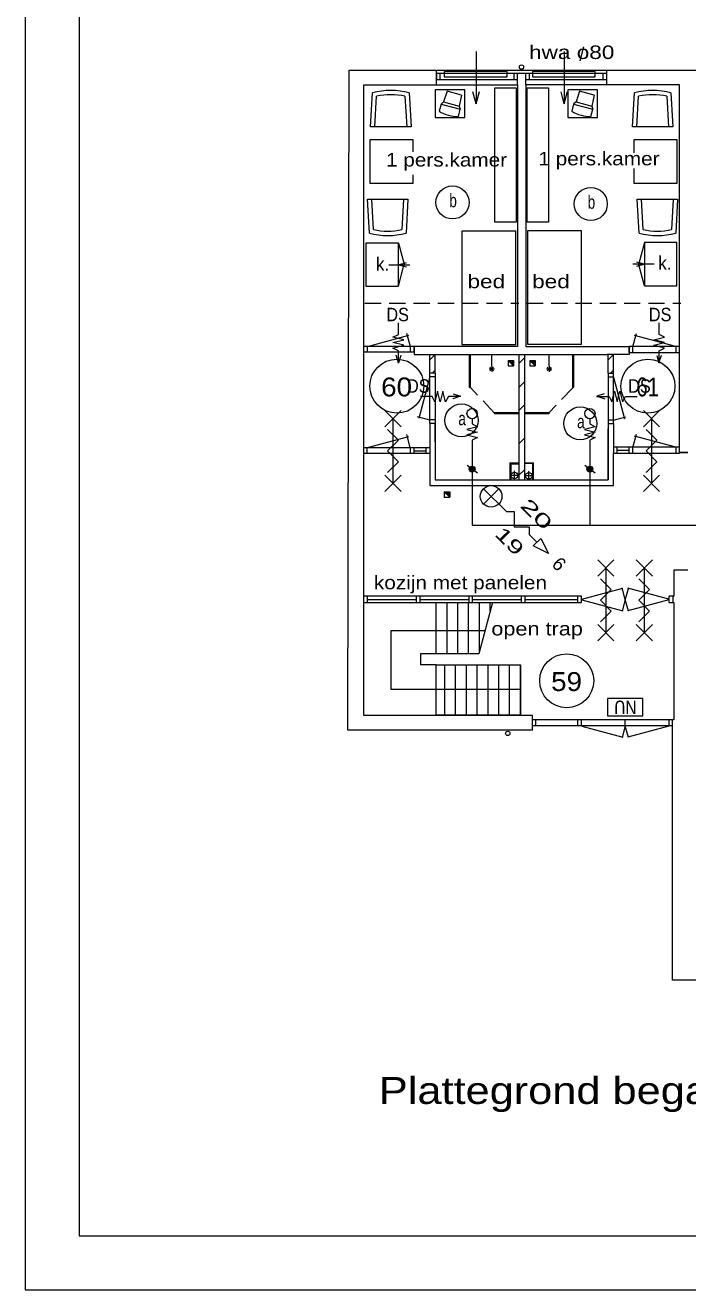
# Model space of a CAD drawing. Extents: x 295824 to 414724, y 24924 to 109024.
# Drawn here: x 295824 to 308090, y 24924 to 48360 of the extents above; entities that cross this region are included whole.
import ezdxf
from ezdxf.enums import TextEntityAlignment as Align

# ---------------------------------------------------------------- set-up
doc = ezdxf.new("R2010")
doc.units = 0
doc.header["$LTSCALE"] = 100
doc.linetypes.add('DOT_DASHED', pattern=[7.7, 5, -1.2, 0.3, -1.2])
doc.linetypes.add('MEDIUM_DASHED', pattern=[4.5, 3, -1.5])
for name, color, linetype, lineweight in [('1', 7, 'Continuous', 13), ('16', 7, 'Continuous', 13), ('24', 7, 'Continuous', 13), ('61', 7, 'Continuous', 13)]:
    doc.layers.add(name, color=color, linetype=linetype, lineweight=lineweight)

msp = doc.modelspace()

# ---------------------------------------------------------------- hatches: boundary and pattern name
at = {"layer": '24'}
for points in [[(304151.5, 40135, 1), (304042.9, 40135, 1)], [(306333.5, 40135, 1), (306224.9, 40135, 1)]]:
    msp.add_hatch(color=256, dxfattribs=at).paths.add_polyline_path(points)
at = {"layer": '61'}
for points in [[(304864.2, 42048.6), (304764.2, 42148.6), (304864.2, 42148.6)], [(305267.2, 42048.6), (305167.2, 42148.6), (305267.2, 42148.6)], [(303682.7, 39611.2), (303582.7, 39711.2), (303682.7, 39711.2)]]:
    msp.add_hatch(color=256, dxfattribs=at).paths.add_polyline_path(points)

# ---------------------------------------------------------------- linework, layer by layer
at = {"layer": '1'}
for p, q in [((295823.6, 109023.8), (295823.6, 24923.8)), ((304097.2, 40103.6), (304097.2, 39093.2)), ((306279.2, 40097), (306279.2, 39093.2)), ((295823.6, 24923.8), (304995.6, 24923.8)), ((304995.6, 24923.8), (414723.6, 24923.8))]:
    msp.add_line(p, q, dxfattribs=at)
for points in [[(304995.6, 108023.8), (296823.6, 108023.8), (296823.6, 25923.8), (304995.6, 25923.8)], [(304995.6, 25923.8), (413723.6, 25923.8), (413723.6, 108023.8), (304995.6, 108023.8)]]:
    msp.add_lwpolyline(points, dxfattribs=at)
at = {"layer": '16'}
for p, q in [((302631.4, 42478.5), (302831.4, 42528.5)), ((307661.7, 42478.5), (307461.7, 42528.5)), ((303507.8, 41380.3), (303457.8, 41580.3)), ((306785.3, 41380.3), (306835.3, 41580.3))]:
    msp.add_line(p, q, dxfattribs=at)
at = {"layer": '24'}
for p, q in [((304172.2, 46901.4), (304112.5, 47123.8)), ((305804.5, 46901.4), (305744.9, 47123.8)), ((302734.8, 42103.1), (302689.8, 42247.3)), ((302777.2, 42238.9), (302734.8, 42103.1)), ((307515.9, 42238.9), (307558.3, 42103.1)), ((307558.3, 42103.1), (307603.3, 42247.3)), ((303883.2, 41483.7), (303739, 41438.7)), ((303747.4, 41526.2), (303883.2, 41483.7)), ((306545.7, 41526.2), (306409.9, 41483.7)), ((306409.9, 41483.7), (306554, 41438.7)), ((304097.2, 40620.3), (304097.2, 40080.9)), ((306279.2, 40620.3), (306279.2, 40112)), ((304005.6, 40205.8), (304197.1, 40064.1)), ((306187.6, 40205.8), (306379.1, 40064.1)), ((304097.2, 39093.2), (328693.9, 39093.2))]:
    msp.add_line(p, q, dxfattribs=at)
for points in [[(304172.2, 47876.3), (304172.2, 46901.4), (304233.8, 47131.6)], [(305804.5, 47876.3), (305804.5, 46901.4), (305866.2, 47131.6)], [(302831.4, 42528.5), (302631.4, 42578.5), (302731.4, 42628.5), (302731.4, 42847.3)], [(307461.7, 42528.5), (307661.7, 42578.5), (307561.7, 42628.5), (307561.7, 42847.3)], [(302731.4, 42097.3), (302731.4, 42328.5), (302631.4, 42378.5), (302831.4, 42428.5), (302631.4, 42478.5)], [(307561.7, 42097.3), (307561.7, 42328.5), (307661.7, 42378.5), (307461.7, 42428.5), (307661.7, 42478.5)], [(303457.8, 41580.3), (303407.8, 41380.3), (303357.8, 41480.3), (303139.1, 41480.3)], [(303889.1, 41480.3), (303657.8, 41480.3), (303607.8, 41380.3), (303557.8, 41580.3), (303507.8, 41380.3)], [(306404, 41480.3), (306635.3, 41480.3), (306685.3, 41380.3), (306735.3, 41580.3), (306785.3, 41380.3)], [(306835.3, 41580.3), (306885.3, 41380.3), (306935.3, 41480.3), (307154, 41480.3)], [(304097.2, 41070.3), (304097.2, 40970.3), (304197.2, 40920.3), (303997.2, 40870.3), (304197.2, 40820.3), (303997.2, 40770.3), (304197.2, 40720.3), (304097.2, 40670.3), (304097.2, 40620.3)], [(306279.2, 41070.3), (306279.2, 40970.3), (306379.2, 40920.3), (306179.2, 40870.3), (306379.2, 40820.3), (306179.2, 40770.3), (306379.2, 40720.3), (306279.2, 40670.3), (306279.2, 40620.3)]]:
    msp.add_lwpolyline(points, dxfattribs=at)
for points in [[(303580.8, 47405.5), (304746.8, 47405.5), (304746.8, 47505.5), (303580.8, 47505.5)], [(305213.2, 47405.5), (306379.1, 47405.5), (306379.1, 47505.5), (305213.2, 47505.5)]]:
    msp.add_lwpolyline(points, close=True, dxfattribs=at)
for centre, radius in [((304097.2, 41162), 95), ((306279.2, 41162), 95), ((304097.2, 40135), 54.3), ((306279.2, 40135), 54.3)]:
    msp.add_circle(centre, radius, dxfattribs=at)
at = {"layer": '61'}
for p, q in [((301796.6, 35294.8), (301820.1, 47527.9)), ((301828.9, 47527.9), (333452, 47527.9)), ((303440.8, 47257.3), (303440.8, 47527.3)), ((303441.6, 47472.1), (304940.6, 47472.1)), ((303441.6, 47358.1), (303441.6, 47472.1)), ((303441.6, 47358.1), (304939.7, 47358.1)), ((303508.6, 47358.1), (303508.6, 47471.5)), ((304873.6, 47472.1), (306589.6, 47472.1)), ((304873.6, 47358.5), (304873.6, 47472.1)), ((304940.6, 47359.1), (304940.6, 47472.1)), ((304940.8, 47257.3), (304940.8, 47472.1)), ((305089.8, 47257.3), (305089.8, 47472.1)), ((305090.6, 47358.1), (305090.6, 47472.1)), ((305090.6, 47358.1), (306588.7, 47358.1)), ((305157.6, 47358.1), (305157.6, 47471.5)), ((306522.6, 47358.5), (306522.6, 47471.5)), ((306589.6, 47359.1), (306589.6, 47472.1)), ((306589.8, 47257.3), (306589.8, 47527.3)), ((302090.1, 40535.6), (302090.1, 47257.9)), ((302218.1, 46478.4), (302253, 47107.7)), ((303632.8, 47140.4), (303568.8, 46940.1)), ((303903.3, 47067.9), (303632.8, 47140.4)), ((306088.6, 47140.4), (306024.6, 46940.1)), ((306359, 47067.9), (306088.6, 47140.4)), ((307067.6, 46478.4), (307102.6, 47107.7)), ((307940.1, 40540.2), (307940.1, 47257.9)), ((302298.2, 46478.4), (302329.6, 47044.3)), ((302854.4, 47044.2), (302887.9, 46478.4)), ((303522.1, 46900.8), (303485.9, 46765.9)), ((303568.8, 46940.1), (303522.1, 46900.8)), ((303522.1, 46900.8), (303879.5, 46805.1)), ((303903.3, 47067.9), (303858.6, 46862.5)), ((305977.8, 46900.8), (305941.7, 46765.9)), ((306024.6, 46940.1), (305977.8, 46900.8)), ((305977.8, 46900.8), (306335.2, 46805.1)), ((306359, 47067.9), (306314.4, 46862.5)), ((307147.8, 46478.4), (307179.2, 47044.3)), ((307704, 47044.2), (307737.5, 46478.4)), ((303843.2, 46669.8), (303879.5, 46805.1)), ((306299, 46669.8), (306335.2, 46805.1)), ((303004.6, 46013), (303004.6, 46235.3)), ((307095.4, 45707.2), (307095.4, 45435.3)), ((303004.6, 45435.3), (303004.6, 45590.5)), ((302204.6, 45435.3), (303004.6, 45435.3)), ((302273, 44572.7), (302239.6, 45138.5)), ((302829.2, 45138.5), (302797.8, 44572.6)), ((302909.4, 45138.5), (302874.4, 44509.2)), ((307267.1, 44572.7), (307233.6, 45138.5)), ((307823.3, 45138.5), (307791.9, 44572.6)), ((307903.4, 45138.5), (307868.5, 44509.2)), ((302732.3, 44322.5), (302836.7, 43932.9)), ((307287.9, 44331.3), (307184.6, 43945.7)), ((302552.5, 43922.5), (302946.8, 43922.5)), ((302732.3, 43922.5), (302880.1, 43962)), ((302732.3, 43922.5), (302880.6, 43882.7)), ((302732.3, 43522.5), (302835.7, 43908.1)), ((307467.7, 43931.3), (307073.4, 43931.3)), ((307287.9, 43931.3), (307139.6, 43971)), ((307287.9, 43931.3), (307140.2, 43891.7)), ((307287.9, 43531.3), (307183.5, 43920.9)), ((302160.1, 42409.2), (302927.4, 42614.8)), ((302954.7, 42407.1), (302889.7, 42649.8)), ((307076.5, 42405.1), (307141.5, 42647.8)), ((307871.1, 42407.2), (307103.8, 42612.8)), ((303022.4, 42299.4), (302091.6, 42299.4)), ((302157.5, 42299.1), (302157.5, 42409.1)), ((302957.5, 42299.1), (302957.5, 42409.1)), ((303024.5, 42299.1), (303024.5, 42409.1)), ((303025.4, 42257.9), (306615.6, 42257.9)), ((303315.2, 41911.5), (303315.2, 42257.9)), ((303315.2, 42157.2), (303415.7, 42257.6)), ((303414, 41911.5), (303414, 42257.9)), ((304047.9, 41644.6), (304047.9, 42253)), ((304065.9, 41644.6), (304065.9, 42253)), ((304460.8, 42039.2), (304460.8, 42239.2)), ((304965.1, 42257.9), (304965.1, 39932.9)), ((304965.6, 42093), (305064.1, 42191.5)), ((305065.1, 42257.9), (305065.1, 39932.9)), ((305525.3, 42039.2), (305525.3, 42239.2)), ((305965.7, 41650.7), (305965.7, 42255.5)), ((305983.7, 41650.7), (305983.7, 42255.5)), ((306615.6, 41911.9), (306615.6, 42258.3)), ((306615.7, 42157.2), (306716.2, 42257.6)), ((306715.4, 41911.5), (306715.4, 42257.9)), ((307006.7, 42297.1), (307006.7, 42407.1)), ((307008.8, 42297.4), (307939.6, 42297.4)), ((307073.7, 42297.1), (307073.7, 42407.1)), ((307873.7, 42297.1), (307873.7, 42407.1)), ((303357.6, 41913.2), (303414.3, 41969.9)), ((304510.8, 41989.2), (304410.8, 41989.2)), ((304496.2, 42024.5), (304425.4, 41953.8)), ((304496.2, 41953.8), (304425.4, 42024.5)), ((304460.8, 42039.2), (304460.8, 41939.2)), ((305575.3, 41989.2), (305475.3, 41989.2)), ((305560.6, 42024.5), (305489.9, 41953.8)), ((305560.6, 41953.8), (305489.9, 42024.5)), ((305525.3, 42039.2), (305525.3, 41939.2)), ((306659.5, 41913.2), (306716.2, 41969.9)), ((303315.3, 41841.3), (303108.4, 41069.1)), ((303315, 40977.9), (303315, 41911.9)), ((303415, 41911.9), (303315, 41911.9)), ((303415.2, 41844.9), (303315, 41844.9)), ((303415, 41911.9), (303415, 40977.9)), ((304965.6, 41645.4), (305064.1, 41743.9)), ((306615, 41844.5), (306715.1, 41844.5)), ((306615.1, 41911.5), (306615.1, 40977.5)), ((306615.6, 41911.5), (306715.7, 41911.5)), ((306714.9, 41841), (306921.8, 41068.7)), ((306715.1, 40976.7), (306715.1, 41911.5)), ((304047.9, 41644.6), (304065.9, 41644.6)), ((305965.7, 41650.7), (305983.7, 41650.7)), ((306715.2, 41578.4), (306715.2, 41468)), ((304965.6, 41222.9), (305064.1, 41321.4)), ((302482.1, 40919.8), (302782.1, 41219.8)), ((302782.1, 40919.8), (302482.1, 41219.8)), ((302632.1, 41069.8), (302632.1, 39869.8)), ((303315.3, 41043.9), (303088, 41104.8)), ((303414.9, 41044.9), (303315.5, 41044.9)), ((304964.8, 41158.7), (304514.4, 41158.7)), ((305516.2, 41176.7), (305066.1, 41176.7)), ((305516.2, 41158.7), (305066.1, 41158.7)), ((305516.2, 41176.7), (305516.2, 41158.7)), ((306615.3, 41044.5), (306714.6, 41044.5)), ((306714.9, 41043.5), (306942.2, 41104.4)), ((307269.7, 40919.8), (307569.7, 41219.8)), ((307569.7, 40919.8), (307269.7, 41219.8)), ((307419.7, 41069.8), (307419.7, 39869.8)), ((303415, 40977.9), (303315, 40977.9)), ((303315.1, 40975.3), (303315.1, 40188.2)), ((303415.1, 40638.2), (303415.1, 40975.3)), ((306615.1, 40977.5), (306615.1, 39932.9)), ((306615.1, 40977.5), (306715.1, 40977.5)), ((306715.1, 40977.5), (306715.1, 40532.9)), ((307076.5, 40536.8), (307141.5, 40779.5)), ((302158.9, 40535.1), (302926.2, 40740.7)), ((302953.5, 40532.9), (302888.4, 40775.7)), ((304965.6, 40603), (305064.1, 40701.4)), ((307871.1, 40539), (307103.8, 40744.6)), ((302090.1, 37776.3), (302090.1, 40424.1)), ((302156.3, 40424.9), (302156.3, 40534.9)), ((302956.3, 40424.9), (302956.3, 40534.9)), ((303023.3, 40424.9), (303023.3, 40534.9)), ((303024.1, 40475.7), (303248.8, 40475.7)), ((303248.8, 40424.9), (303248.8, 40534.9)), ((306781.2, 40428.8), (306781.2, 40538.8)), ((307005.8, 40479.6), (306781.2, 40479.6)), ((307006.7, 40428.8), (307006.7, 40538.8)), ((307073.7, 40428.8), (307073.7, 40538.8)), ((307873.7, 40428.8), (307873.7, 40538.8)), ((307939.5, 40447.3), (308089.5, 40447.3)), ((307939.5, 40443.5), (308089.5, 40443.5)), ((304797.5, 40248.9), (304965.3, 40248.9)), ((304797.5, 40248.9), (304797.5, 39935.2)), ((304812.5, 40233.9), (304964.4, 40233.9)), ((304812.5, 40233.9), (304812.5, 39934.9)), ((304967.7, 40024.9), (305065, 40122.2)), ((305065.1, 40250.3), (305235.7, 40250.3)), ((305220.8, 40235.1), (305065.1, 40235.1)), ((305220.8, 39933.5), (305220.8, 40235.1)), ((305235.7, 39932.9), (305235.7, 40250.3)), ((302482.1, 39719.8), (302782.1, 40019.8)), ((302782.1, 39719.8), (302482.1, 40019.8)), ((307269.7, 39719.8), (307569.7, 40019.8)), ((307569.7, 39719.8), (307269.7, 40019.8)), ((304591, 39769.8), (304308.1, 39487)), ((306423.7, 38152.6), (306723.7, 38452.6)), ((306723.7, 38152.6), (306423.7, 38452.6)), ((307135.6, 38152.6), (307435.6, 38452.6)), ((307435.6, 38152.6), (307135.6, 38452.6)), ((306573.7, 38302.6), (306573.7, 37102.6)), ((307285.6, 38302.6), (307285.6, 37102.6)), ((306122.8, 37776.3), (302090.1, 37776.3)), ((302092, 37664.3), (302092, 37776.3)), ((302159, 37663.7), (302159, 37775.7)), ((303067.5, 37663.7), (303067.5, 37775.7)), ((303134.5, 37663.7), (303134.5, 37775.7)), ((304040.9, 37663.7), (304040.9, 37775.7)), ((304107.9, 37663.7), (304107.9, 37775.7)), ((305014.3, 37663.7), (305014.3, 37775.7)), ((305081.3, 37663.7), (305081.3, 37775.7)), ((306055.8, 37664.3), (306055.8, 37776.3)), ((306122.8, 37664.3), (306122.8, 37776.3)), ((306126.8, 37723.2), (306888.3, 37927.2)), ((306933.6, 37720.1), (306876.1, 37934.8)), ((306991.8, 37936.1), (306934, 37720.4)), ((307742.8, 37723.2), (306979.5, 37927.7)), ((307743.8, 37664.3), (307743.8, 37776.3)), ((307832.8, 37776.3), (307743.8, 37776.3)), ((307821.9, 37662.7), (307821.9, 37776.7)), ((302090.1, 35564.8), (302090.1, 37664.3)), ((302090.1, 37664.3), (306122.8, 37664.3)), ((302159.1, 37715), (303066.1, 37715)), ((303131, 37715), (304038, 37715)), ((303433.4, 36710), (303433.4, 37662.3)), ((303633.4, 36710), (303633.4, 37662.3)), ((303833.4, 36710), (303833.4, 37662.3)), ((304033.4, 36710), (304033.4, 37662.3)), ((304108.4, 37715), (305015.4, 37715)), ((304477.3, 37658.7), (304220.7, 36710)), ((304233.4, 36757.1), (304233.4, 37662.3)), ((304433.4, 37505.9), (304433.4, 37661.1)), ((305078.1, 37715), (306039.3, 37715)), ((306126.8, 37711.6), (306888.3, 37507.6)), ((306933.6, 37714.7), (306876.1, 37500)), ((306991.8, 37498.7), (306934, 37714.4)), ((307742.8, 37711.6), (306979.5, 37507.1)), ((307743.8, 37664.3), (307832.8, 37664.3)), ((307832.8, 37664.3), (307832.8, 35486.8)), ((306423.7, 36952.6), (306723.7, 37252.6)), ((306723.7, 36952.6), (306423.7, 37252.6)), ((307135.6, 36952.6), (307435.6, 37252.6)), ((307435.6, 36952.6), (307135.6, 37252.6)), ((303433.4, 36710), (303140.1, 36710)), ((303140.1, 36710), (303140.1, 36507.9)), ((303433.4, 36507.9), (303140.1, 36507.9)), ((303592.8, 35570.1), (303592.8, 36507.9)), ((303792.8, 35570.1), (303792.8, 36507.9)), ((303992.8, 35570.1), (303992.8, 36507.9)), ((304192.8, 35570.1), (304192.8, 36507.9)), ((304392.8, 35570.1), (304392.8, 36507.9)), ((304592.8, 35570.1), (304592.8, 36507.9)), ((304792.8, 35570.1), (304792.8, 36507.9)), ((304992.8, 35570.1), (304992.8, 36507.9)), ((305213.7, 35564.8), (302090.1, 35564.8)), ((305213.7, 35294.8), (305213.7, 35564.8)), ((307832.8, 35486.8), (305219.5, 35486.8)), ((305278.5, 35372), (305278.5, 35486)), ((306055.8, 35372), (306055.8, 35486)), ((306122.8, 35372), (306122.8, 35486)), ((306933.7, 35372.8), (306933.7, 35486)), ((307743.8, 35372), (307743.8, 35486)), ((307806, 30663.6), (307811.6, 35486.8)), ((305213.7, 35294.8), (301796.6, 35294.8)), ((307811.4, 35372.8), (305218.4, 35372.8)), ((306126.8, 35369.5), (306888.3, 35165.5)), ((306933.6, 35372.6), (306876.1, 35157.9)), ((306991.8, 35156.6), (306934, 35372.2)), ((307742.8, 35369.5), (306979.5, 35165)), ((326190, 30663.6), (307806, 30663.6))]:
    msp.add_line(p, q, dxfattribs=at)
at = {"layer": '61', "linetype": 'MEDIUM_DASHED'}
for p, q in [((302112.4, 43208.1), (304962.4, 43208.1)), ((305112.4, 43208.1), (307962.4, 43208.1)), ((304507.1, 41179.8), (304065.2, 41644.8)), ((305961.3, 41643.1), (305517.3, 41175.8))]:
    msp.add_line(p, q, dxfattribs=at)
at = {"layer": '61', "linetype": 'DOT_DASHED'}
for p, q in [((304881.5, 39934.8), (304881.5, 40098.9)), ((305145.3, 39934.3), (305145.3, 40093.7)), ((304970.7, 40016), (304806.6, 40016)), ((305230.4, 40008.6), (305066.4, 40008.6)), ((305230.6, 40008.6), (305066.5, 40008.6))]:
    msp.add_line(p, q, dxfattribs=at)
at = {"layer": '61'}
for points in [[(302090.1, 47257.9), (304940.1, 47257.9), (304940.1, 42407.4)], [(302930.8, 47107.7), (302968, 46478.4), (302218.1, 46478.4)], [(307940.1, 47257.9), (305090.1, 47257.9), (305090.1, 42407.9), (307032.6, 42407.9)], [(307780.4, 47107.7), (307817.6, 46478.4), (307067.6, 46478.4)], [(303568.8, 46940.1), (303858.6, 46862.5), (303879.5, 46805.1)], [(306024.6, 46940.1), (306314.4, 46862.5), (306335.2, 46805.1)], [(303004.6, 46235.3), (302204.6, 46235.3), (302204.6, 45435.3)], [(307095.4, 45435.3), (307895.4, 45435.3), (307895.4, 46235.3), (307095.4, 46235.3), (307095.4, 45999.1)], [(302196.6, 44509.2), (302159.4, 45138.5), (302909.4, 45138.5)], [(307190.7, 44509.2), (307153.5, 45138.5), (307903.4, 45138.5)], [(302091.6, 42299.4), (302091.6, 42409.8), (303025, 42409.8)], [(304940.1, 42407.9), (303025.4, 42407.9), (303025.4, 42257.9)], [(307006.2, 42407.8), (307006.2, 42257.9), (306600.8, 42257.9)], [(307939.6, 42297.4), (307939.6, 42407.8), (307006.2, 42407.8)], [(304764.2, 42148.6), (304864.2, 42148.6), (304864.2, 42048.6)], [(305167.2, 42148.6), (305267.2, 42148.6), (305267.2, 42048.6)], [(303415.1, 41158.7), (303415.1, 39932.9), (305295.1, 39932.9)], [(304964.8, 41176.7), (304514.4, 41176.7), (304514.4, 41158.7)], [(302532.1, 40869.8), (302732.1, 40669.8), (302532.1, 40469.8), (302732.1, 40269.8), (302532.1, 40069.8)], [(305090, 39932.9), (306615.1, 39932.9), (306615.1, 40882.9)], [(307319.7, 40869.8), (307519.7, 40669.8), (307319.7, 40469.8), (307519.7, 40269.8), (307319.7, 40069.8)], [(303315.1, 40432.9), (303315.1, 39832.9), (306715.1, 39832.9), (306715.1, 40432.9)], [(303582.7, 39711.2), (303682.7, 39711.2), (303682.7, 39611.2)], [(304308.1, 39769.8), (304732.4, 39345.6), (304873.8, 39345.6), (304873.8, 39062.7), (305156.6, 39062.7), (305156.6, 38921.3), (305298, 38779.8)], [(308090.1, 38258.6), (307832.8, 38258.6), (307832.8, 37776.3)], [(306473.7, 38102.6), (306673.7, 37902.6), (306473.7, 37702.6), (306673.7, 37502.6), (306473.7, 37302.6)], [(307185.6, 38102.6), (307385.6, 37902.6), (307185.6, 37702.6), (307385.6, 37502.6), (307185.6, 37302.6)], [(304220.7, 36710), (303433.4, 36710), (303433.4, 37662.3), (304478.2, 37662.3)], [(304992.8, 36046.2), (302596, 36046.2), (302596, 37142.8), (304343.1, 37142.8)]]:
    msp.add_lwpolyline(points, dxfattribs=at)
for points in [[(303961.1, 47162), (303415, 47162), (303415, 46653.9), (303961.1, 46653.9)], [(304516.2, 44708.9), (304516.2, 47202.5), (304916.2, 47202.5), (304916.2, 44708.9)], [(305114.7, 44708.9), (305114.7, 47202.5), (305514.7, 47202.5), (305514.7, 44708.9)], [(306416.9, 47162), (305870.7, 47162), (305870.7, 46653.9), (306416.9, 46653.9)], [(303906, 42446.4), (304906, 42446.4), (304906, 44546.4), (303906, 44546.4)], [(305120.9, 42451.5), (306120.9, 42451.5), (306120.9, 44551.5), (305120.9, 44551.5)], [(302132.3, 43522.5), (302732.3, 43522.5), (302732.3, 44322.5), (302132.3, 44322.5)], [(307887.9, 44331.3), (307287.9, 44331.3), (307287.9, 43531.3), (307887.9, 43531.3)], [(304764.2, 42148.6), (304764.2, 42048.6), (304864.2, 42048.6)], [(304864.2, 42048.6), (304764.2, 42148.6), (304864.2, 42148.6)], [(305167.2, 42148.6), (305167.2, 42048.6), (305267.2, 42048.6)], [(305267.2, 42048.6), (305167.2, 42148.6), (305267.2, 42148.6)], [(302090.4, 40425.3), (302090.4, 40535.6), (303314.7, 40535.6), (303314.7, 40425.3)], [(307939.6, 40429.1), (307939.6, 40539.5), (306715.2, 40539.5), (306715.2, 40429.1)], [(303582.7, 39711.2), (303582.7, 39611.2), (303682.7, 39611.2)], [(303682.7, 39611.2), (303582.7, 39711.2), (303682.7, 39711.2)], [(305227.3, 38709.2), (305368.8, 38850.6), (305510.2, 38567.7)], [(304992.8, 35570.1), (303433.4, 35570.1), (303433.4, 36507.9), (304992.8, 36507.9)], [(307260.2, 35879.4), (306603.6, 35879.4), (306603.6, 35558.4), (307260.2, 35558.4)]]:
    msp.add_lwpolyline(points, close=True, dxfattribs=at)
for centre, radius in [((305012.3, 47584.2), 40), ((303733.9, 45076.2), 306.3), ((306295.3, 45048.3), 306.3), ((302703.6, 41671.6), 500), ((307353, 41671.6), 500), ((303900.9, 41036.3), 306.3), ((306100.4, 40980.6), 306.3), ((304881.5, 40015.2), 62.5), ((305146, 40009.3), 62.5), ((304449.5, 39628.4), 200), ((305849.6, 36210.8), 500), ((304758.9, 35235.3), 40)]:
    msp.add_circle(centre, radius, dxfattribs=at)
for centre, radius, start, end in [((302591.8, 45868), 1285.2, 74.70731, 105.28507), ((307441.4, 45868), 1285.2, 74.70731, 105.28507), ((302591.8, 45868), 1205.2, 77.41626, 102.56606), ((307441.4, 45868), 1205.2, 77.41626, 102.56606), ((303848.2, 47400.6), 730.8, 240.27982, 269.60839), ((306304, 47400.6), 730.8, 240.27982, 269.60839), ((302535.6, 45748.9), 1205.2, 257.41626, 282.56606), ((307529.6, 45748.9), 1205.2, 257.41626, 282.56606), ((302535.6, 45748.9), 1285.2, 254.70731, 285.28507), ((307529.6, 45748.9), 1285.2, 254.70731, 285.28507)]:
    msp.add_arc(centre, radius, start, end, dxfattribs=at)

# ---------------------------------------------------------------- texts
at = {"layer": '24', "width": 0.9}
for p in [(302509.6, 42874.3), (307370.2, 42874.3), (302892.7, 41549.3), (306987.1, 41549.3)]:
    msp.add_text('DS', height=250, dxfattribs=at).set_placement(p)
at = {"layer": '61'}
for s, height, width, p in [('hwa o80', 250, 1.25, (305152.3, 47735.3)), ('1 pers.kamer', 250, 1.15, (302502.5, 45742.2)), ('1 pers.kamer', 250, 1.15, (305324.8, 45764.4)), ('b', 250, 0.75, (303675.9, 44987)), ('b', 250, 0.75, (306237.3, 44959.2)), ('k.', 250, 0.95, (302315.8, 43809.4)), ('k.', 250, 0.95, (307545.2, 43830)), (' bed', 250, 1.25, (303896, 43487.3)), (' bed', 250, 1.25, (305093, 43487.3)), ('a', 250, 0.75, (303842.9, 40947.1)), ('a', 250, 0.75, (306042.4, 40891.4)), ('kozijn met panelen', 250, 1.15, (302279.1, 37906.2)), ('open trap', 250, 1.2, (304453.7, 37051.1)), ('Plattegrond begane grond.', 500, 1.2, (302371.3, 28366.7))]:
    msp.add_text(s, height=height, dxfattribs=dict(at, width=width)).set_placement(p)
msp.add_text('/', height=250, dxfattribs=at).set_placement((306082.3, 47700.2))
for s, width, p in [('60', 1.1, (302699.2, 41481.7)), ('61', 0.8, (307348.7, 41481.7)), ('59', 1.1, (305846.7, 36020.9))]:
    msp.add_text(s, height=350, dxfattribs=dict(at, width=width)).set_placement(p, align=Align.CENTER)
for s, width, p in [('20', 1.75, (304972, 39443.2)), ('19', 1.55, (304499.8, 38914.7))]:
    msp.add_text(s, height=250, rotation=315, dxfattribs=dict(at, width=width)).set_placement(p)
msp.add_text('6', height=250, rotation=315, dxfattribs=at).set_placement((305556, 38353.2))
at = {"layer": '61', "width": 0.85}
msp.add_text('NU', height=250, rotation=180, dxfattribs=at).set_placement((306935.4, 35842.5), align=Align.CENTER)

doc.saveas('drawing.dxf')
